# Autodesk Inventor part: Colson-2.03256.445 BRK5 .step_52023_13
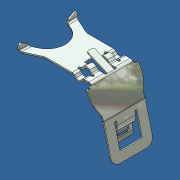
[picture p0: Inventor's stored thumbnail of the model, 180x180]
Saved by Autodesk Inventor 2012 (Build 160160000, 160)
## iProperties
Created: 2010-10
Part Number: Colson-2.03256.445 BRK5 .step_52023_13
Document SubType Name: Modeling
Designer: Administrator
Density: 7.85 g/cm^3
Material: Steel
Mass: 34.2353 g
Surface Area: 84.1634 cm^2
Volume: 4.36118 cm^3
Author: Administrator
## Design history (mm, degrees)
feature "Base1"
body "Solid1"
